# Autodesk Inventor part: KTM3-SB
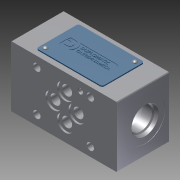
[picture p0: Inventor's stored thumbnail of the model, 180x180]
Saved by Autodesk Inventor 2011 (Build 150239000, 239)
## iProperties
Created: 2012-01
Part Number: KTM3-SB
Document SubType Name: Modeling
Designer: khramov
Density: 1 g/cm^3
Author: khramov
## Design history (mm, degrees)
derived "KTM3_SB_10N.iam"
node "Твердое тело1"
node "0144336.ipt:1"
sketch "3001110000.ipt:1"
sketch "0530521.ipt:1"
sketch "0530521.ipt:2"
